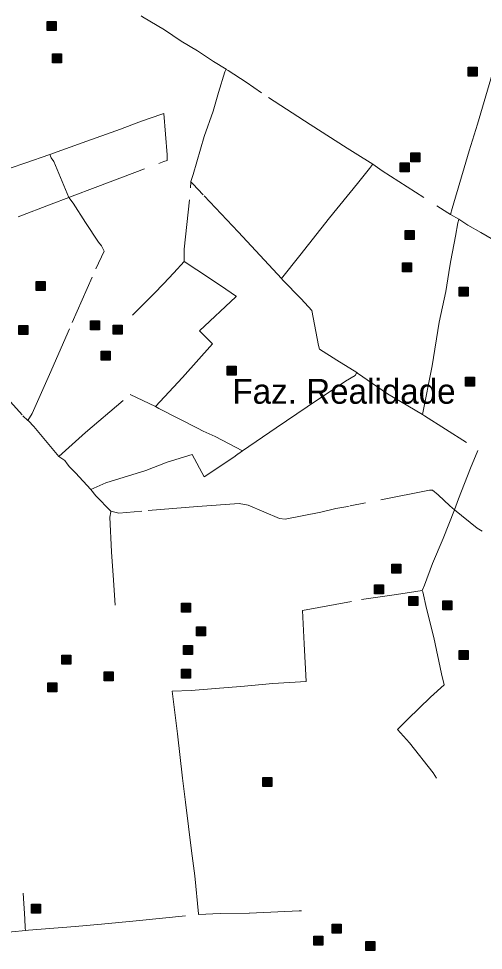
# Model space of a CAD drawing. Extents: x 393.5 to 446.9, y 8064.8 to 8120.4.
# Drawn here: x 416.31 to 419.31, y 8076.08 to 8082.08 of the extents above; entities that cross this region are included whole.
import ezdxf

# ---------------------------------------------------------------- set-up
doc = ezdxf.new("R2010")
doc.units = 0
doc.header["$LTSCALE"] = 0.064
doc.linetypes.add('DOT_DASHED', pattern=[7.7, 5, -1.2, 0.3, -1.2])
doc.layers.add('2', color=7, linetype='Continuous', lineweight=25)
doc.layers.add('22', color=7, linetype='DOT_DASHED', lineweight=13)
doc.layers.add('61', color=7, linetype='Continuous')

msp = doc.modelspace()

# ---------------------------------------------------------------- hatches: boundary and pattern name
at = {"layer": '2'}
for points in [[(416.497, 8082.0605), (416.555, 8082.0605), (416.555, 8082.0025), (416.497, 8082.0025)], [(416.5317, 8081.8519), (416.5897, 8081.8519), (416.5897, 8081.7939), (416.5317, 8081.7939)], [(419.2117, 8081.7646), (419.2697, 8081.7646), (419.2697, 8081.7066), (419.2117, 8081.7066)], [(418.8427, 8081.214), (418.9007, 8081.214), (418.9007, 8081.156), (418.8427, 8081.156)], [(418.7724, 8081.1501), (418.8304, 8081.1501), (418.8304, 8081.0921), (418.7724, 8081.0921)], [(418.8049, 8080.7133), (418.8629, 8080.7133), (418.8629, 8080.6553), (418.8049, 8080.6553)], [(418.7885, 8080.5055), (418.8465, 8080.5055), (418.8465, 8080.4475), (418.7885, 8080.4475)], [(416.4256, 8080.3845), (416.4836, 8080.3845), (416.4836, 8080.3265), (416.4256, 8080.3265)], [(419.1546, 8080.3493), (419.2126, 8080.3493), (419.2126, 8080.2913), (419.1546, 8080.2913)], [(416.776, 8080.132), (416.834, 8080.132), (416.834, 8080.074), (416.776, 8080.074)], [(416.3142, 8080.1019), (416.3722, 8080.1019), (416.3722, 8080.0439), (416.3142, 8080.0439)], [(416.9228, 8080.1046), (416.9808, 8080.1046), (416.9808, 8080.0466), (416.9228, 8080.0466)], [(416.8457, 8079.9357), (416.9037, 8079.9357), (416.9037, 8079.8777), (416.8457, 8079.8777)], [(417.6571, 8079.8393), (417.7151, 8079.8393), (417.7151, 8079.7813), (417.6571, 8079.7813)], [(419.1948, 8079.7692), (419.2528, 8079.7692), (419.2528, 8079.7112), (419.1948, 8079.7112)], [(418.7202, 8078.5652), (418.7782, 8078.5652), (418.7782, 8078.5072), (418.7202, 8078.5072)], [(418.6082, 8078.4318), (418.6662, 8078.4318), (418.6662, 8078.3738), (418.6082, 8078.3738)], [(417.3625, 8078.3138), (417.4205, 8078.3138), (417.4205, 8078.2558), (417.3625, 8078.2558)], [(418.829, 8078.3566), (418.887, 8078.3566), (418.887, 8078.2986), (418.829, 8078.2986)], [(419.0491, 8078.3288), (419.1071, 8078.3288), (419.1071, 8078.2708), (419.0491, 8078.2708)], [(417.4605, 8078.1604), (417.5185, 8078.1604), (417.5185, 8078.1024), (417.4605, 8078.1024)], [(417.3764, 8078.0412), (417.4344, 8078.0412), (417.4344, 8077.9832), (417.3764, 8077.9832)], [(416.5922, 8077.9777), (416.6502, 8077.9777), (416.6502, 8077.9197), (416.5922, 8077.9197)], [(419.154, 8078.0074), (419.212, 8078.0074), (419.212, 8077.9494), (419.154, 8077.9494)], [(416.8658, 8077.8714), (416.9238, 8077.8714), (416.9238, 8077.8134), (416.8658, 8077.8134)], [(417.3624, 8077.8873), (417.4204, 8077.8873), (417.4204, 8077.8293), (417.3624, 8077.8293)], [(416.502, 8077.8004), (416.56, 8077.8004), (416.56, 8077.7424), (416.502, 8077.7424)], [(417.887, 8077.1904), (417.945, 8077.1904), (417.945, 8077.1324), (417.887, 8077.1324)], [(416.3968, 8076.3731), (416.4548, 8076.3731), (416.4548, 8076.3151), (416.3968, 8076.3151)], [(418.3349, 8076.2456), (418.3929, 8076.2456), (418.3929, 8076.1876), (418.3349, 8076.1876)], [(418.2159, 8076.1679), (418.2739, 8076.1679), (418.2739, 8076.1099), (418.2159, 8076.1099)], [(418.5518, 8076.1344), (418.6098, 8076.1344), (418.6098, 8076.0764), (418.5518, 8076.0764)]]:
    msp.add_hatch(color=256, dxfattribs=at).paths.add_polyline_path(points)

# ---------------------------------------------------------------- linework, layer by layer
for points in [[(416.497, 8082.0605), (416.555, 8082.0605), (416.555, 8082.0025), (416.497, 8082.0025)], [(416.5317, 8081.8519), (416.5897, 8081.8519), (416.5897, 8081.7939), (416.5317, 8081.7939)], [(419.2117, 8081.7646), (419.2697, 8081.7646), (419.2697, 8081.7066), (419.2117, 8081.7066)], [(418.8427, 8081.214), (418.9007, 8081.214), (418.9007, 8081.156), (418.8427, 8081.156)], [(418.7724, 8081.1501), (418.8304, 8081.1501), (418.8304, 8081.0921), (418.7724, 8081.0921)], [(418.8049, 8080.7133), (418.8629, 8080.7133), (418.8629, 8080.6553), (418.8049, 8080.6553)], [(418.7885, 8080.5055), (418.8465, 8080.5055), (418.8465, 8080.4475), (418.7885, 8080.4475)], [(416.4256, 8080.3845), (416.4836, 8080.3845), (416.4836, 8080.3265), (416.4256, 8080.3265)], [(419.1546, 8080.3493), (419.2126, 8080.3493), (419.2126, 8080.2913), (419.1546, 8080.2913)], [(416.776, 8080.132), (416.834, 8080.132), (416.834, 8080.074), (416.776, 8080.074)], [(416.3142, 8080.1019), (416.3722, 8080.1019), (416.3722, 8080.0439), (416.3142, 8080.0439)], [(416.9228, 8080.1046), (416.9808, 8080.1046), (416.9808, 8080.0466), (416.9228, 8080.0466)], [(416.8457, 8079.9357), (416.9037, 8079.9357), (416.9037, 8079.8777), (416.8457, 8079.8777)], [(417.6571, 8079.8393), (417.7151, 8079.8393), (417.7151, 8079.7813), (417.6571, 8079.7813)], [(419.1948, 8079.7692), (419.2528, 8079.7692), (419.2528, 8079.7112), (419.1948, 8079.7112)], [(418.7202, 8078.5652), (418.7782, 8078.5652), (418.7782, 8078.5072), (418.7202, 8078.5072)], [(418.6082, 8078.4318), (418.6662, 8078.4318), (418.6662, 8078.3738), (418.6082, 8078.3738)], [(417.3625, 8078.3138), (417.4205, 8078.3138), (417.4205, 8078.2558), (417.3625, 8078.2558)], [(418.829, 8078.3566), (418.887, 8078.3566), (418.887, 8078.2986), (418.829, 8078.2986)], [(419.0491, 8078.3288), (419.1071, 8078.3288), (419.1071, 8078.2708), (419.0491, 8078.2708)], [(417.4605, 8078.1604), (417.5185, 8078.1604), (417.5185, 8078.1024), (417.4605, 8078.1024)], [(417.3764, 8078.0412), (417.4344, 8078.0412), (417.4344, 8077.9832), (417.3764, 8077.9832)], [(416.5922, 8077.9777), (416.6502, 8077.9777), (416.6502, 8077.9197), (416.5922, 8077.9197)], [(419.154, 8078.0074), (419.212, 8078.0074), (419.212, 8077.9494), (419.154, 8077.9494)], [(416.8658, 8077.8714), (416.9238, 8077.8714), (416.9238, 8077.8134), (416.8658, 8077.8134)], [(417.3624, 8077.8873), (417.4204, 8077.8873), (417.4204, 8077.8293), (417.3624, 8077.8293)], [(416.502, 8077.8004), (416.56, 8077.8004), (416.56, 8077.7424), (416.502, 8077.7424)], [(417.887, 8077.1904), (417.945, 8077.1904), (417.945, 8077.1324), (417.887, 8077.1324)], [(416.3968, 8076.3731), (416.4548, 8076.3731), (416.4548, 8076.3151), (416.3968, 8076.3151)], [(418.3349, 8076.2456), (418.3929, 8076.2456), (418.3929, 8076.1876), (418.3349, 8076.1876)], [(418.2159, 8076.1679), (418.2739, 8076.1679), (418.2739, 8076.1099), (418.2159, 8076.1099)], [(418.5518, 8076.1344), (418.6098, 8076.1344), (418.6098, 8076.0764), (418.5518, 8076.0764)]]:
    msp.add_lwpolyline(points, close=True, dxfattribs=at)
at = {"layer": '22'}
msp.add_line((416.636, 8080.9259), (416.6405, 8080.9276), dxfattribs=at)
for points in [[(417.1024, 8082.096), (417.1115, 8082.0903), (417.2534, 8082.0055), (417.3606, 8081.9336), (417.4665, 8081.8712), (417.5696, 8081.8021), (417.6511, 8081.7519)], [(419.218, 8081.2277), (419.272, 8081.3983), (419.3572, 8081.6906), (419.3849, 8081.786), (419.4698, 8082.0501)], [(417.6511, 8081.7519), (417.6422, 8081.7361), (417.6015, 8081.6018), (417.5675, 8081.4825), (417.5096, 8081.3187), (417.4387, 8081.0745), (417.4227, 8081.0288)], [(418.4313, 8081.2447), (418.1939, 8081.3963), (417.8783, 8081.6003), (417.7793, 8081.6696), (417.6639, 8081.7442), (417.6515, 8081.7516), (417.6511, 8081.7519)], [(417.2714, 8081.1864), (417.2714, 8081.2008), (417.2503, 8081.4681), (417.154, 8081.436), (417.0887, 8081.4115)], [(417.0887, 8081.4115), (416.9691, 8081.3663), (416.723, 8081.2781), (416.5151, 8081.203)], [(416.5141, 8081.2027), (416.3536, 8081.1475), (416.2662, 8081.1172)], [(416.636, 8080.9259), (416.5401, 8081.1589), (416.524, 8081.1821), (416.5151, 8081.203), (416.5141, 8081.2027)], [(418.5963, 8081.1398), (418.484, 8081.2114), (418.4313, 8081.2447)], [(419.0968, 8080.817), (419.1076, 8080.855), (419.1197, 8080.8925), (419.1969, 8081.1542), (419.218, 8081.2277)], [(416.6405, 8080.9276), (416.8248, 8080.9979), (417.2503, 8081.1579), (417.2717, 8081.165), (417.2717, 8081.1775), (417.2714, 8081.1864)], [(418.0072, 8080.4042), (418.127, 8080.5523), (418.3184, 8080.795), (418.4983, 8081.016), (418.5763, 8081.1137), (418.5958, 8081.1392), (418.5963, 8081.1398)], [(418.5963, 8081.1398), (418.6564, 8081.0988), (419.0805, 8080.8265), (419.0968, 8080.817)], [(417.3813, 8080.5145), (417.3814, 8080.5938), (417.4224, 8080.9879), (417.4227, 8081.0255), (417.4227, 8081.0288)], [(418.0072, 8080.4042), (417.8979, 8080.5226), (417.7296, 8080.7055), (417.5025, 8080.9438), (417.4355, 8081.0141), (417.4256, 8081.0254), (417.4227, 8081.0288)], [(416.636, 8080.9259), (416.5231, 8080.883), (416.3096, 8080.8013)], [(416.8293, 8080.6384), (416.7443, 8080.7645), (416.6658, 8080.8893), (416.636, 8080.9259)], [(419.1524, 8080.7874), (419.0983, 8080.8162), (419.0968, 8080.817)], [(419.0998, 8080.5209), (419.1306, 8080.6776), (419.146, 8080.7628), (419.1516, 8080.7844), (419.1524, 8080.7874)], [(419.1524, 8080.7874), (419.2086, 8080.7474), (419.2941, 8080.7013), (419.4149, 8080.6294), (419.5534, 8080.5467), (419.5967, 8080.5212), (419.5993, 8080.5197)], [(416.3737, 8079.49), (416.4, 8079.534), (416.5133, 8079.786), (416.6585, 8080.1208), (416.8109, 8080.4655), (416.8639, 8080.5793), (416.8475, 8080.6152), (416.8293, 8080.6384)], [(417.0481, 8080.1687), (417.1868, 8080.3071), (417.2473, 8080.3692), (417.3143, 8080.441), (417.3813, 8080.5145)], [(417.1968, 8079.5795), (417.3699, 8079.7667), (417.5643, 8079.9839), (417.4794, 8080.0672), (417.7171, 8080.2892), (417.6142, 8080.3594), (417.4613, 8080.4606), (417.3813, 8080.5145)], [(418.9181, 8079.5276), (418.9792, 8079.8411), (419.0252, 8080.1223), (419.0668, 8080.3209), (419.0939, 8080.4836), (419.0998, 8080.5209)], [(418.0072, 8080.4042), (418.0152, 8080.3959), (418.1344, 8080.2725), (418.2035, 8080.1989), (418.2466, 8079.9735), (418.254, 8079.9496), (418.3658, 8079.8782), (418.4928, 8079.7985)], [(416.1197, 8079.7609), (416.3411, 8079.5194), (416.3737, 8079.49)], [(418.1742, 8079.5778), (418.4198, 8079.7427), (418.4821, 8079.7794), (418.4928, 8079.7985)], [(418.4928, 8079.7985), (418.4951, 8079.7969), (418.4976, 8079.7952)], [(418.4976, 8079.7952), (418.6923, 8079.6617), (418.9181, 8079.5277)], [(416.5733, 8079.2584), (416.7447, 8079.4118), (417.0318, 8079.6563), (417.1955, 8079.5801), (417.1968, 8079.5795)], [(417.5037, 8079.4218), (417.4659, 8079.4393), (417.218, 8079.5665), (417.1968, 8079.5795)], [(417.7572, 8079.2952), (417.9744, 8079.4422), (418.1742, 8079.5778)], [(418.9181, 8079.5277), (418.9309, 8079.5201), (419.2789, 8079.299)], [(416.5733, 8079.2584), (416.4113, 8079.4508), (416.3769, 8079.4867), (416.3762, 8079.4874), (416.3737, 8079.49)], [(417.7572, 8079.2952), (417.5802, 8079.3855), (417.5037, 8079.4218)], [(416.7792, 8079.0451), (416.8763, 8079.0887), (417.1345, 8079.1671), (417.2701, 8079.221), (417.4319, 8079.2716), (417.5087, 8079.1263), (417.7067, 8079.2572), (417.7254, 8079.2727), (417.7264, 8079.2733), (417.7572, 8079.2952)], [(419.2748, 8079.2967), (419.226, 8079.1818), (419.1497, 8078.984), (419.123, 8078.9151), (419.1225, 8078.9139)], [(416.5733, 8079.2584), (416.6106, 8079.2321), (416.6253, 8079.2109), (416.6416, 8079.1912)], [(416.6416, 8079.1912), (416.681, 8079.1525), (416.7792, 8079.0451)], [(416.7792, 8079.0451), (416.8107, 8079.0044), (416.9079, 8078.9059)], [(419.1225, 8078.9139), (419.0936, 8078.94), (419.0177, 8079.0103), (418.9825, 8079.0399), (418.9621, 8079.0399), (418.4435, 8078.9382), (418.4225, 8078.9344)], [(418.4225, 8078.9344), (418.3575, 8078.9234), (418.2611, 8078.8993), (418.0314, 8078.8549), (417.9943, 8078.8586), (417.7923, 8078.9437), (417.7349, 8078.9548), (417.4672, 8078.9347), (417.1084, 8078.9057), (416.9596, 8078.8919), (416.9079, 8078.9059)], [(419.1225, 8078.9139), (419.0513, 8078.73), (418.9815, 8078.5687), (418.9292, 8078.4285), (418.9143, 8078.3952)], [(419.1225, 8078.9139), (419.2689, 8078.7959), (419.3014, 8078.7758)], [(416.9366, 8078.2996), (416.9244, 8078.4605), (416.9114, 8078.6438), (416.9012, 8078.866), (416.9069, 8078.9002), (416.9079, 8078.9059)], [(417.7468, 8077.7757), (417.9516, 8077.7945), (418.1672, 8077.8083), (418.1547, 8078.052), (418.1441, 8078.2647), (418.5234, 8078.3359), (418.7346, 8078.3656), (418.8328, 8078.3822), (418.9143, 8078.3952)], [(419.0083, 8077.1851), (418.9855, 8077.22), (418.8333, 8077.4123), (418.7564, 8077.4992), (418.8225, 8077.5653), (418.9693, 8077.7083), (419.0572, 8077.7863), (419.0394, 8077.8574), (418.9893, 8078.0914), (418.9428, 8078.278), (418.9199, 8078.3859), (418.9145, 8078.3949), (418.9143, 8078.3952)], [(417.4722, 8076.3127), (417.4489, 8076.5571), (417.4274, 8076.7173), (417.3882, 8077.03), (417.3704, 8077.1865), (417.3382, 8077.4715), (417.3034, 8077.745), (417.4257, 8077.7505), (417.6091, 8077.7653), (417.7468, 8077.7757)], [(416.3424, 8076.444), (416.353, 8076.2794), (416.356, 8076.2223), (416.3575, 8076.204)], [(418.1379, 8076.3321), (418.1218, 8076.332), (417.7987, 8076.3151), (417.6134, 8076.3133), (417.4726, 8076.3077)], [(416.3575, 8076.204), (416.3766, 8076.2057), (416.6769, 8076.2297), (416.8467, 8076.2461), (417.0709, 8076.2666), (417.4726, 8076.3077)], [(417.4726, 8076.3077), (417.4723, 8076.3112), (417.4722, 8076.3127)], [(416.3575, 8076.204), (416.1594, 8076.1855), (415.9091, 8076.1638), (415.6893, 8076.1404), (415.6155, 8076.1328), (415.5914, 8076.1327)]]:
    msp.add_lwpolyline(points, dxfattribs=at)

# ---------------------------------------------------------------- texts
at = {"layer": '61'}
msp.add_text('Faz. Realidade', height=0.16, dxfattribs=at).set_placement((417.6916, 8079.5976))

doc.saveas('drawing.dxf')
